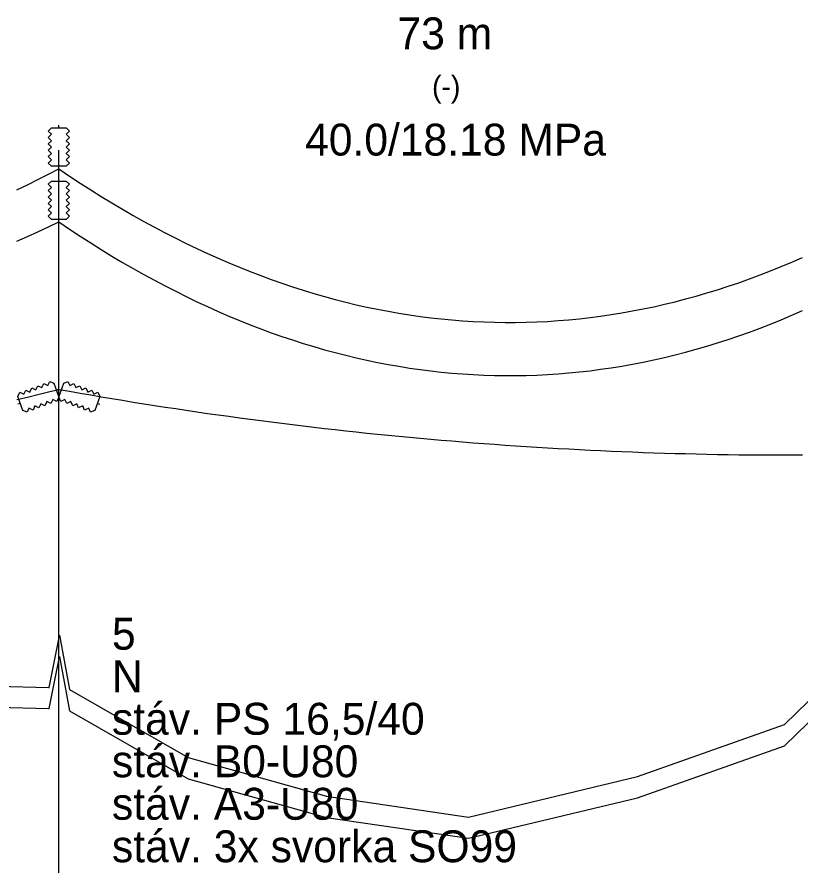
# Model space of a CAD drawing. Extents: x -21 to 628, y 809 to 990.
# Drawn here: x 314.9 to 388.6, y 910 to 989.8 of the extents above; entities that cross this region are included whole.
import ezdxf

# ---------------------------------------------------------------- set-up
doc = ezdxf.new("R2010")
doc.units = 0
for name, color, linetype in [('Vrstva 11', 7, 'Continuous'), ('Vrstva 12', 7, 'Continuous'), ('Vrstva 13', 7, 'Continuous'), ('Vrstva 14', 7, 'Continuous'), ('Vrstva 15', 7, 'Continuous'), ('Vrstva 29', 7, 'Continuous'), ('Vrstva 3', 7, 'Continuous')]:
    doc.layers.add(name, color=color, linetype=linetype)

msp = doc.modelspace()

# ---------------------------------------------------------------- linework, layer by layer
at = {"layer": 'Vrstva 11'}
for points in [[(314.9, 973.516), (315.9, 973.991), (316.9, 974.483), (317.9, 974.991), (318.861, 975.494)], [(318.861, 975.494), (319.861, 974.821), (320.861, 974.163), (321.861, 973.522), (322.861, 972.897), (323.861, 972.287), (324.861, 971.694), (325.861, 971.117), (326.861, 970.556), (327.861, 970.011), (328.861, 969.483), (329.861, 968.97), (330.861, 968.473), (331.861, 967.992), (332.861, 967.528), (333.861, 967.079), (334.861, 966.647), (335.861, 966.231), (336.861, 965.83), (337.861, 965.446), (338.861, 965.078), (339.861, 964.726), (340.861, 964.39), (341.861, 964.07), (342.861, 963.766), (343.861, 963.478), (344.861, 963.206), (345.861, 962.95), (346.861, 962.711), (347.861, 962.487), (348.861, 962.279), (349.861, 962.088), (350.861, 961.912), (351.861, 961.753), (352.861, 961.61), (353.861, 961.483), (354.861, 961.371), (355.861, 961.276), (356.861, 961.197), (357.861, 961.134), (358.861, 961.087), (359.861, 961.057), (360.861, 961.042), (361.861, 961.043), (362.861, 961.06), (363.861, 961.094), (364.861, 961.143), (365.861, 961.209), (366.861, 961.291), (367.861, 961.388), (368.861, 961.502), (369.861, 961.632), (370.861, 961.778), (371.861, 961.94), (372.861, 962.118), (373.861, 962.312), (374.861, 962.522), (375.861, 962.748), (376.861, 962.99), (377.861, 963.249), (378.861, 963.523), (379.861, 963.813), (380.861, 964.12), (381.861, 964.443), (382.861, 964.781), (383.861, 965.136), (384.861, 965.507), (385.861, 965.894), (386.861, 966.296), (387.861, 966.715), (388.861, 967.15)], [(314.9, 968.685), (315.9, 969.118), (316.9, 969.567), (317.9, 970.032), (318.861, 970.494)], [(314.9, 968.685), (315.9, 969.118), (316.9, 969.567), (317.9, 970.032), (318.861, 970.494)], [(318.861, 970.494), (319.861, 969.821), (320.861, 969.163), (321.861, 968.522), (322.861, 967.897), (323.861, 967.287), (324.861, 966.694), (325.861, 966.117), (326.861, 965.556), (327.861, 965.011), (328.861, 964.483), (329.861, 963.97), (330.861, 963.473), (331.861, 962.993), (332.861, 962.528), (333.861, 962.079), (334.861, 961.647), (335.861, 961.231), (336.861, 960.83), (337.861, 960.446), (338.861, 960.078), (339.861, 959.726), (340.861, 959.39), (341.861, 959.07), (342.861, 958.766), (343.861, 958.478), (344.861, 958.206), (345.861, 957.95), (346.861, 957.711), (347.861, 957.487), (348.861, 957.279), (349.861, 957.088), (350.861, 956.913), (351.861, 956.753), (352.861, 956.61), (353.861, 956.483), (354.861, 956.372), (355.861, 956.276), (356.861, 956.197), (357.861, 956.134), (358.861, 956.088), (359.861, 956.057), (360.861, 956.042), (361.861, 956.043), (362.861, 956.061), (363.861, 956.094), (364.861, 956.143), (365.861, 956.209), (366.861, 956.291), (367.861, 956.388), (368.861, 956.502), (369.861, 956.632), (370.861, 956.778), (371.861, 956.94), (372.861, 957.118), (373.861, 957.312), (374.861, 957.522), (375.861, 957.748), (376.861, 957.99), (377.861, 958.249), (378.861, 958.523), (379.861, 958.813), (380.861, 959.12), (381.861, 959.443), (382.861, 959.781), (383.861, 960.136), (384.861, 960.507), (385.861, 960.894), (386.861, 961.296), (387.861, 961.715), (388.861, 962.15)], [(318.861, 970.494), (319.861, 969.821), (320.861, 969.163), (321.861, 968.522), (322.861, 967.897), (323.861, 967.287), (324.861, 966.694), (325.861, 966.117), (326.861, 965.556), (327.861, 965.011), (328.861, 964.483), (329.861, 963.97), (330.861, 963.473), (331.861, 962.993), (332.861, 962.528), (333.861, 962.079), (334.861, 961.647), (335.861, 961.231), (336.861, 960.83), (337.861, 960.446), (338.861, 960.078), (339.861, 959.726), (340.861, 959.39), (341.861, 959.07), (342.861, 958.766), (343.861, 958.478), (344.861, 958.206), (345.861, 957.95), (346.861, 957.711), (347.861, 957.487), (348.861, 957.279), (349.861, 957.088), (350.861, 956.913), (351.861, 956.753), (352.861, 956.61), (353.861, 956.483), (354.861, 956.372), (355.861, 956.276), (356.861, 956.197), (357.861, 956.134), (358.861, 956.088), (359.861, 956.057), (360.861, 956.042), (361.861, 956.043), (362.861, 956.061), (363.861, 956.094), (364.861, 956.143), (365.861, 956.209), (366.861, 956.291), (367.861, 956.388), (368.861, 956.502), (369.861, 956.632), (370.861, 956.778), (371.861, 956.94), (372.861, 957.118), (373.861, 957.312), (374.861, 957.522), (375.861, 957.748), (376.861, 957.99), (377.861, 958.249), (378.861, 958.523), (379.861, 958.813), (380.861, 959.12), (381.861, 959.443), (382.861, 959.781), (383.861, 960.136), (384.861, 960.507), (385.861, 960.894), (386.861, 961.296), (387.861, 961.715), (388.861, 962.15)], [(314.9, 953.774), (315.9, 954.015), (316.9, 954.259), (317.9, 954.505), (318.861, 954.744)], [(318.861, 954.744), (319.861, 954.566), (320.861, 954.39), (321.861, 954.217), (322.861, 954.047), (323.861, 953.879), (324.861, 953.714), (325.861, 953.551), (326.861, 953.391), (327.861, 953.234), (328.861, 953.079), (329.861, 952.927), (330.861, 952.778), (331.861, 952.631), (332.861, 952.486), (333.861, 952.345), (334.861, 952.206), (335.861, 952.069), (336.861, 951.935), (337.861, 951.804), (338.861, 951.675), (339.861, 951.549), (340.861, 951.426), (341.861, 951.305), (342.861, 951.187), (343.861, 951.071), (344.861, 950.958), (345.861, 950.848), (346.861, 950.74), (347.861, 950.635), (348.861, 950.533), (349.861, 950.433), (350.861, 950.335), (351.861, 950.241), (352.861, 950.148), (353.861, 950.059), (354.861, 949.972), (355.861, 949.888), (356.861, 949.806), (357.861, 949.727), (358.861, 949.65), (359.861, 949.577), (360.861, 949.505), (361.861, 949.437), (362.861, 949.371), (363.861, 949.307), (364.861, 949.246), (365.861, 949.188), (366.861, 949.133), (367.861, 949.08), (368.861, 949.029), (369.861, 948.981), (370.861, 948.936), (371.861, 948.894), (372.861, 948.854), (373.861, 948.816), (374.861, 948.782), (375.861, 948.75), (376.861, 948.72), (377.861, 948.693), (378.861, 948.669), (379.861, 948.647), (380.861, 948.628), (381.861, 948.612), (382.861, 948.598), (383.861, 948.587), (384.861, 948.578), (385.861, 948.572), (386.861, 948.568), (387.861, 948.568), (388.861, 948.569)]]:
    msp.add_lwpolyline(points, dxfattribs=at)
at = {"layer": 'Vrstva 14'}
msp.add_line((318.861, 901.244), (318.861, 977.244), dxfattribs=at)
at = {"layer": 'Vrstva 29'}
for points in [[(319.561, 975.744), (318.161, 975.744), (317.861, 976.044), (318.161, 976.344), (317.861, 976.644), (318.161, 976.944), (317.861, 977.244), (318.161, 977.544), (317.861, 977.844), (318.161, 978.144), (317.861, 978.444), (318.161, 978.744), (317.861, 979.044), (318.161, 979.344), (319.561, 979.344), (319.861, 979.044), (319.561, 978.744), (319.861, 978.444), (319.561, 978.144), (319.861, 977.844), (319.561, 977.544), (319.861, 977.244), (319.561, 976.944), (319.861, 976.644), (319.561, 976.344), (319.861, 976.044)], [(319.561, 970.744), (318.161, 970.744), (317.861, 971.044), (318.161, 971.344), (317.861, 971.644), (318.161, 971.944), (317.861, 972.244), (318.161, 972.544), (317.861, 972.844), (318.161, 973.144), (317.861, 973.444), (318.161, 973.744), (317.861, 974.044), (318.161, 974.344), (319.561, 974.344), (319.861, 974.044), (319.561, 973.744), (319.861, 973.444), (319.561, 973.144), (319.861, 972.844), (319.561, 972.544), (319.861, 972.244), (319.561, 971.944), (319.861, 971.644), (319.561, 971.344), (319.861, 971.044)], [(319.561, 970.744), (318.161, 970.744), (317.861, 971.044), (318.161, 971.344), (317.861, 971.644), (318.161, 971.944), (317.861, 972.244), (318.161, 972.544), (317.861, 972.844), (318.161, 973.144), (317.861, 973.444), (318.161, 973.744), (317.861, 974.044), (318.161, 974.344), (319.561, 974.344), (319.861, 974.044), (319.561, 973.744), (319.861, 973.444), (319.561, 973.144), (319.861, 972.844), (319.561, 972.544), (319.861, 972.244), (319.561, 971.944), (319.861, 971.644), (319.561, 971.344), (319.861, 971.044)], [(318.387, 955.316), (318.866, 954.001), (318.687, 953.616), (318.302, 953.795), (318.123, 953.411), (317.738, 953.59), (317.559, 953.206), (317.174, 953.385), (316.995, 953), (316.611, 953.18), (316.431, 952.795), (316.047, 952.975), (315.867, 952.59), (315.483, 952.769), (315.004, 954.085), (315.183, 954.469), (315.568, 954.29), (315.747, 954.675), (316.132, 954.495), (316.311, 954.88), (316.696, 954.701), (316.875, 955.085), (317.259, 954.906), (317.439, 955.29), (317.823, 955.111), (318.002, 955.496)], [(318.857, 954.001), (319.336, 955.316), (319.72, 955.496), (319.899, 955.111), (320.284, 955.29), (320.463, 954.906), (320.848, 955.085), (321.027, 954.701), (321.412, 954.88), (321.591, 954.495), (321.975, 954.675), (322.155, 954.29), (322.539, 954.469), (322.719, 954.085), (322.24, 952.769), (321.855, 952.59), (321.676, 952.975), (321.291, 952.795), (321.112, 953.18), (320.728, 953), (320.548, 953.385), (320.164, 953.206), (319.984, 953.59), (319.6, 953.411), (319.421, 953.795), (319.036, 953.616)]]:
    msp.add_lwpolyline(points, close=True, dxfattribs=at)
for points in [[(318.861, 979.344), (318.861, 979.594)], [(318.861, 975.494), (318.861, 975.744)], [(318.861, 974.344), (318.861, 974.594)], [(318.861, 974.344), (318.861, 974.594)], [(318.861, 970.494), (318.861, 970.744)], [(318.861, 970.494), (318.861, 970.744)], [(318.861, 954.744), (318.626, 954.658)], [(318.861, 954.744), (319.096, 954.658)], [(315.243, 953.427), (315.009, 953.342)], [(322.479, 953.427), (322.714, 953.342)]]:
    msp.add_lwpolyline(points, dxfattribs=at)
at = {"layer": 'Vrstva 3'}
for p, q in [((318.861, 931.244), (318.934, 931.6)), ((318.934, 931.6), (319.854, 926.5)), ((317.938, 926.7), (318.861, 931.244)), ((317.938, 924.7), (318.861, 929.244)), ((317.938, 924.7), (318.861, 929.244)), ((317.938, 924.7), (318.861, 929.244)), ((318.861, 929.244), (318.934, 929.6)), ((318.861, 929.244), (318.934, 929.6)), ((318.861, 929.244), (318.934, 929.6)), ((318.934, 929.6), (319.854, 924.5)), ((318.934, 929.6), (319.854, 924.5)), ((318.934, 929.6), (319.854, 924.5)), ((312.134, 926.85), (317.902, 926.7)), ((317.902, 926.7), (317.938, 926.7)), ((319.854, 926.5), (331.027, 920.1)), ((387.181, 923.2), (390.605, 926.55)), ((312.134, 924.85), (317.902, 924.7)), ((312.134, 924.85), (317.902, 924.7)), ((312.134, 924.85), (317.902, 924.7)), ((317.902, 924.7), (317.938, 924.7)), ((317.902, 924.7), (317.938, 924.7)), ((317.902, 924.7), (317.938, 924.7)), ((319.854, 924.5), (331.027, 918.1)), ((319.854, 924.5), (331.027, 918.1)), ((319.854, 924.5), (331.027, 918.1)), ((387.181, 921.2), (390.605, 924.55)), ((387.181, 921.2), (390.605, 924.55)), ((387.181, 921.2), (390.605, 924.55)), ((373.325, 918.3), (387.181, 923.2)), ((373.325, 916.3), (387.181, 921.2)), ((373.325, 916.3), (387.181, 921.2)), ((373.325, 916.3), (387.181, 921.2)), ((331.027, 920.1), (344.067, 916.45)), ((331.027, 918.1), (344.067, 914.45)), ((331.027, 918.1), (344.067, 914.45)), ((331.027, 918.1), (344.067, 914.45)), ((357.434, 914.5), (373.325, 918.3)), ((344.067, 916.45), (357.434, 914.5)), ((357.434, 912.5), (373.325, 916.3)), ((357.434, 912.5), (373.325, 916.3)), ((357.434, 912.5), (373.325, 916.3)), ((344.067, 914.45), (357.434, 912.5)), ((344.067, 914.45), (357.434, 912.5)), ((344.067, 914.45), (357.434, 912.5))]:
    msp.add_line(p, q, dxfattribs=at)

# ---------------------------------------------------------------- texts
at = {"layer": 'Vrstva 12'}
msp.add_text('40.0/18.18 MPa', height=3, dxfattribs=at).set_placement((342.038, 976.744))
at = {"layer": 'Vrstva 13'}
for s, height, p in [('73 m', 3, (350.736, 986.744)), ('(-)', 2, (353.99, 982.244))]:
    msp.add_text(s, height=height, dxfattribs=at).set_placement(p)
at = {"layer": 'Vrstva 15'}
for s, p in [('5', (323.861, 930.244)), ('N', (323.861, 926.244)), ('stáv. PS 16,5/40', (323.861, 922.244)), ('stáv. B0-U80', (323.861, 918.244)), ('stáv. A3-U80', (323.861, 914.244)), ('stáv. 3x svorka SO99', (323.861, 910.244))]:
    msp.add_text(s, height=3, dxfattribs=at).set_placement(p)

doc.saveas('drawing.dxf')
